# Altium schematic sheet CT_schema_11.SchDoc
size 274 x 160 mm
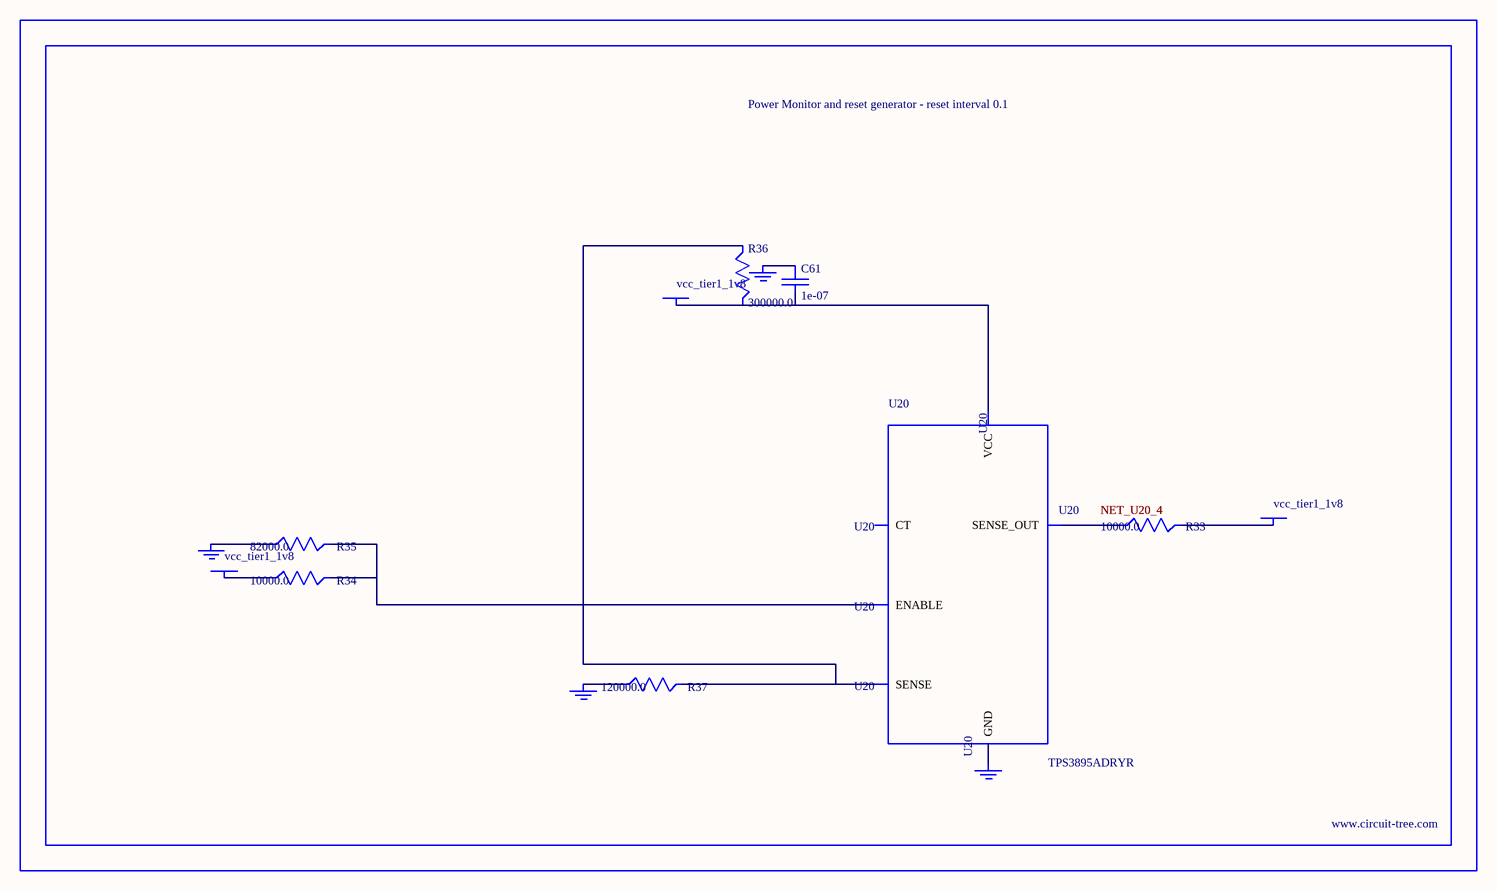
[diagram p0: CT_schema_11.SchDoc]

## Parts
BORDER10  (no value)
C61  1e-07  [C0402]
GND_INSTANCE_10_0  (no value)
GND_INSTANCE_10_1  (no value)
GND_INSTANCE_10_2  (no value)
GND_INSTANCE_10_3  (no value)
POWER_INSTANCE_10_0  vcc_tier1_1v8
POWER_INSTANCE_10_1  vcc_tier1_1v8
POWER_INSTANCE_10_2  vcc_tier1_1v8
R33  10000.0  [R0603]
R34  10000.0  [R0603]
R35  82000.0  [R0603]
R36  300000.0  [R0603]
R37  120000.0  [R0603]
U20  TPS3895ADRYR  [SON-6]

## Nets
NetC61_1: C61.1 GND_INSTANCE_10_2.0(GND)
NetC61_2: C61.2 POWER_INSTANCE_10_2.0(PWR) R36.2 U20.6(VCC)
NetGND_INSTANCE_10_0_0: GND_INSTANCE_10_0.0(GND) R35.1
NetGND_INSTANCE_10_1_0: GND_INSTANCE_10_1.0(GND) R37.1
NetGND_INSTANCE_10_3_0: GND_INSTANCE_10_3.0(GND) U20.2(GND)
NetPOWER_INSTANCE_10_0_0: POWER_INSTANCE_10_0.0(PWR) R34.1
NetPOWER_INSTANCE_10_1_0: POWER_INSTANCE_10_1.0(PWR) R33.2
NetR33_1: R33.1 U20.4(SENSE_OUT)
NetR34_2: R34.2 R35.2 U20.1(ENABLE)
NetR36_1: R36.1 R37.2 U20.3(SENSE)

Not connected (* = marked no-connect by the designer): U20 5(CT)

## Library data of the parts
BORDER10 = BORDER_PAGE10
C61 = C0402C104K3RACTU
GND_INSTANCE_10_0-GND_INSTANCE_10_3 = GND
POWER_INSTANCE_10_0-POWER_INSTANCE_10_2 = PWR
R33 R34 = RC0603JR-0710KL
R35 = RC0603JR-0782KL
R36 = RC0603JR-07300KL
R37 = RC0603JR-07120KL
